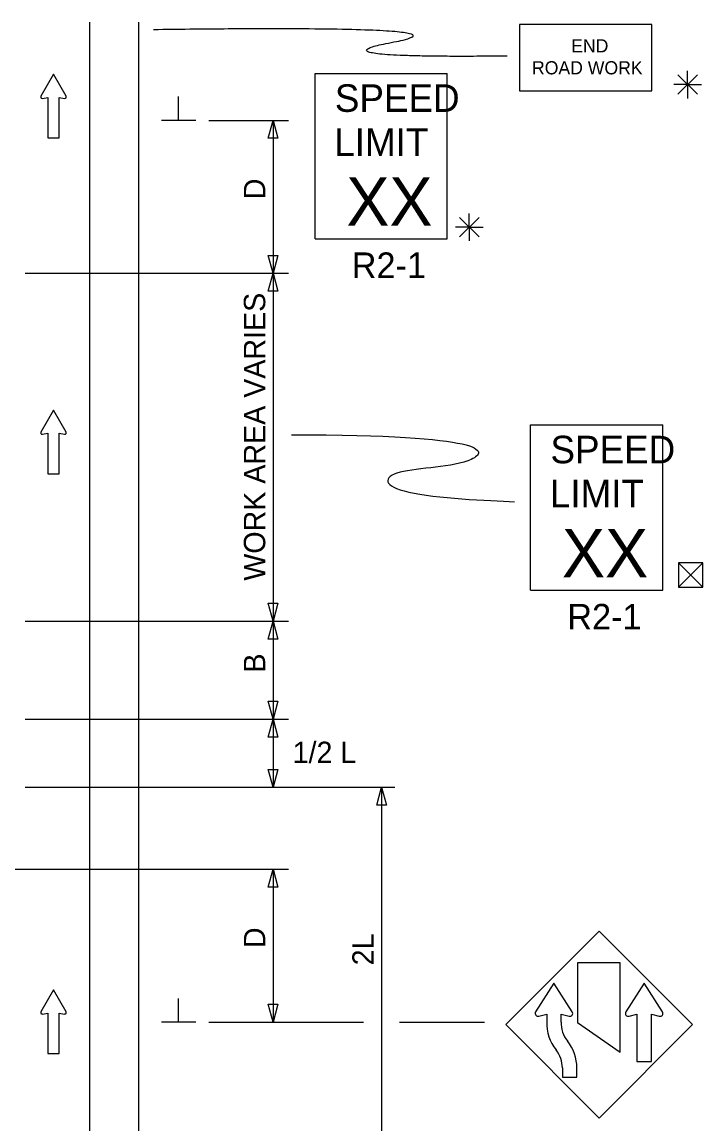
# Model space of a CAD drawing. Extents: x 16726 to 18482, y 5650 to 7013.
# Drawn here: x 16969.3 to 17191.9, y 6566.2 to 6926.4 of the extents above; entities that cross this region are included whole.
import ezdxf

# ---------------------------------------------------------------- set-up
doc = ezdxf.new("R2010")
doc.units = 0
for name, color, linetype in [('MT_SCRATCH_LEVEL_E', 7, 'Continuous'), ('PAVT_EDGE_EX', 7, 'Continuous'), ('TRAFFIC_SIGNS_PR', 7, 'Continuous'), ('TYPICAL_TEXT_DIMEN_PR', 7, 'Continuous')]:
    doc.layers.add(name, color=color, linetype=linetype)

msp = doc.modelspace()

# ---------------------------------------------------------------- linework, layer by layer
at = {"layer": 'MT_SCRATCH_LEVEL_E'}
for p, q in [((16979.53, 6909.41), (16975.42, 6902.17)), ((16983.68, 6902.17), (16979.53, 6909.41)), ((16975.91, 6901.48), (16977.68, 6901.8)), ((16977.68, 6901.8), (16977.68, 6888.54)), ((16981.42, 6888.54), (16981.42, 6901.8)), ((16981.42, 6901.8), (16983.2, 6901.48)), ((16977.68, 6888.54), (16981.42, 6888.54)), ((16979.53, 6799.6), (16975.42, 6792.36)), ((16983.68, 6792.36), (16979.53, 6799.6)), ((16975.91, 6791.67), (16977.68, 6791.99)), ((16977.68, 6791.99), (16977.68, 6778.73)), ((16981.42, 6778.73), (16981.42, 6791.99)), ((16981.42, 6791.99), (16983.2, 6791.67)), ((16977.68, 6778.73), (16981.42, 6778.73)), ((16979.53, 6610.04), (16975.42, 6602.8)), ((16983.68, 6602.8), (16979.53, 6610.04)), ((16975.91, 6602.12), (16977.68, 6602.43)), ((16977.68, 6602.43), (16977.68, 6589.18)), ((16981.42, 6589.18), (16981.42, 6602.43)), ((16981.42, 6602.43), (16983.2, 6602.12)), ((16977.68, 6589.18), (16981.42, 6589.18))]:
    msp.add_line(p, q, dxfattribs=at)
for centre, start, end in [((16975.83, 6901.94), 150.4248, 279.9638), ((16983.27, 6901.94), 260.0362, 29.7731), ((16975.83, 6792.13), 150.4248, 279.9638), ((16983.27, 6792.13), 260.0362, 29.7731), ((16975.83, 6602.58), 150.4248, 279.9638), ((16983.27, 6602.58), 260.0362, 29.7731)]:
    msp.add_arc(centre, 0.463, start, end, dxfattribs=at)
at = {"layer": 'PAVT_EDGE_EX'}
for p, q in [((16991.36, 6926.44), (16991.36, 6057.56)), ((17007.36, 6926.44), (17007.36, 6057.56))]:
    msp.add_line(p, q, dxfattribs=at)
at = {"layer": 'TRAFFIC_SIGNS_PR'}
for p, q in [((17065.08, 6909.61), (17108.28, 6909.61)), ((17065.08, 6855.61), (17065.08, 6909.61)), ((17108.28, 6855.61), (17108.28, 6909.61)), ((17065.08, 6855.61), (17108.28, 6855.61)), ((17135.57, 6794.71), (17178.77, 6794.71)), ((17135.57, 6740.71), (17135.57, 6794.71)), ((17178.77, 6740.71), (17178.77, 6794.71)), ((17135.57, 6740.71), (17178.77, 6740.71)), ((17157.98, 6629.21), (17127.43, 6598.66)), ((17188.53, 6598.66), (17157.98, 6629.21)), ((17127.43, 6598.66), (17157.98, 6568.11)), ((17157.98, 6568.11), (17188.53, 6598.66))]:
    msp.add_line(p, q, dxfattribs=at)
for points in [[(17131.96, 6904), (17175.16, 6904), (17175.16, 6925.6), (17131.96, 6925.6)], [(17150.88, 6618.83), (17150.88, 6599.32), (17164.84, 6589.62), (17164.84, 6618.83)]]:
    msp.add_lwpolyline(points, close=True, dxfattribs=at)
for points in [[(17149.2, 6602.83), (17143.2, 6612.24), (17137.21, 6602.83)], [(17178.7, 6602.83), (17172.71, 6612.24), (17166.72, 6602.83)], [(17138.26, 6601.41), (17140.84, 6602.12), (17140.84, 6599.61)], [(17145.56, 6599.49), (17145.56, 6602.12), (17148.15, 6601.41)], [(17167.77, 6601.41), (17170.35, 6602.12), (17170.35, 6586.59), (17175.07, 6586.59), (17175.07, 6602.12), (17177.66, 6601.41)], [(17145.98, 6584.47), (17145.97, 6581.49), (17150.7, 6581.49), (17150.7, 6584.47)]]:
    msp.add_lwpolyline(points, dxfattribs=at)
for centre, radius, start, end in [((17138.01, 6602.32), 0.945, 147.5204, 285.3986), ((17148.4, 6602.32), 0.947, 254.6828, 32.2708), ((17145.03, 6590.01), 11.81, 74.68, 74.6808), ((17159.16, 6609.16), 11.81, 212.4569, 212.4665), ((17167.52, 6602.32), 0.946, 147.5497, 285.3316), ((17177.91, 6602.32), 0.943, 254.6778, 32.4665), ((17188.67, 6609.16), 11.81, 212.4569, 212.4665), ((17155, 6599.19), 14.17, 178.3293, 218.5427), ((17155, 6599.19), 9.45, 178.1936, 218.5465), ((17133.75, 6599.86), 11.81, 358.1894, 0.0048), ((17136.52, 6584.47), 14.17, 0, 38.5422), ((17136.52, 6584.47), 9.45, 0, 38.5457)]:
    msp.add_arc(centre, radius, start, end, dxfattribs=at)
msp.add_open_spline([(17127.94, 6915.32), (17061.52, 6914.54), (17120.27, 6925.35), (17012.29, 6923.93)], degree=2, dxfattribs=at)
at = {"layer": 'TYPICAL_TEXT_DIMEN_PR'}
for p, q in [((17186.92, 6906), (17186.92, 6910.45)), ((17183.74, 6909.19), (17190.11, 6902.81)), ((17190.11, 6909.19), (17183.74, 6902.81)), ((17186.92, 6906), (17182.39, 6906)), ((17186.92, 6906), (17190.11, 6906)), ((17186.92, 6906), (17191.4, 6906)), ((17186.92, 6906), (17186.92, 6901.5)), ((17020.48, 6894.29), (17020.48, 6902.08)), ((17026.11, 6894.29), (17014.86, 6894.29)), ((17030.36, 6894.29), (17056.36, 6894.29)), ((17049.79, 6888.43), (17051.36, 6894.29)), ((17051.36, 6894.29), (17051.36, 6844.29)), ((17051.36, 6894.29), (17052.93, 6888.43)), ((17051.36, 6888.43), (17049.79, 6888.43)), ((17052.93, 6888.43), (17051.36, 6888.43)), ((17115.53, 6859.37), (17115.53, 6863.82)), ((17112.35, 6862.56), (17118.72, 6856.18)), ((17118.72, 6862.56), (17112.35, 6856.18)), ((17115.53, 6859.37), (17111, 6859.37)), ((17115.53, 6859.37), (17118.72, 6859.37)), ((17115.53, 6859.37), (17120.01, 6859.37)), ((17115.53, 6859.37), (17115.53, 6854.87)), ((17051.36, 6844.29), (17049.79, 6850.15)), ((17049.79, 6850.15), (17051.36, 6850.15)), ((17051.36, 6850.15), (17052.93, 6850.15)), ((17052.93, 6850.15), (17051.36, 6844.29)), ((16970.29, 6844.29), (17056.36, 6844.29)), ((17049.79, 6838.43), (17051.36, 6844.29)), ((17051.36, 6844.29), (17051.36, 6730.57)), ((17051.36, 6844.29), (17052.93, 6838.43)), ((17051.36, 6838.43), (17049.79, 6838.43)), ((17052.93, 6838.43), (17051.36, 6838.43)), ((17183.93, 6749.65), (17191.93, 6741.65)), ((17183.93, 6741.65), (17191.93, 6749.65)), ((17051.36, 6730.57), (17049.79, 6736.43)), ((17049.79, 6736.43), (17051.36, 6736.43)), ((17051.36, 6736.43), (17052.93, 6736.43)), ((17052.93, 6736.43), (17051.36, 6730.57)), ((16970.29, 6730.57), (17056.36, 6730.57)), ((17049.79, 6724.7), (17051.36, 6730.57)), ((17051.36, 6730.57), (17051.36, 6698.49)), ((17051.36, 6730.57), (17052.93, 6724.7)), ((17051.36, 6724.7), (17049.79, 6724.7)), ((17052.93, 6724.7), (17051.36, 6724.7)), ((17051.36, 6705.58), (17051.36, 6701.99)), ((17051.36, 6698.49), (17049.79, 6704.35)), ((17049.79, 6704.35), (17051.36, 6704.35)), ((17051.36, 6704.35), (17052.93, 6704.35)), ((17052.93, 6704.35), (17051.36, 6698.49)), ((16970.29, 6698.49), (17056.36, 6698.49)), ((17049.79, 6692.63), (17051.36, 6698.49)), ((17051.36, 6698.49), (17051.36, 6676.24)), ((17051.36, 6698.49), (17052.93, 6692.63)), ((17051.36, 6692.63), (17049.79, 6692.63)), ((17052.93, 6692.63), (17051.36, 6692.63)), ((17051.36, 6676.24), (17049.79, 6682.11)), ((17049.79, 6682.11), (17051.36, 6682.11)), ((17051.36, 6682.11), (17052.93, 6682.11)), ((17052.93, 6682.11), (17051.36, 6676.24)), ((16970.29, 6676.24), (17091.17, 6676.24)), ((17085.27, 6670.38), (17086.84, 6676.24)), ((17086.84, 6676.24), (17086.84, 6558.37)), ((17086.84, 6676.24), (17088.41, 6670.38)), ((17086.84, 6670.38), (17085.27, 6670.38)), ((17088.41, 6670.38), (17086.84, 6670.38)), ((16951.51, 6649.44), (17056.36, 6649.44)), ((17049.79, 6643.58), (17051.36, 6649.44)), ((17051.36, 6649.44), (17051.36, 6599.44)), ((17051.36, 6649.44), (17052.93, 6643.58)), ((17051.36, 6643.58), (17049.79, 6643.58)), ((17052.93, 6643.58), (17051.36, 6643.58)), ((17020.48, 6599.44), (17020.48, 6607.22)), ((17051.36, 6599.44), (17049.79, 6605.3)), ((17049.79, 6605.3), (17051.36, 6605.3)), ((17051.36, 6605.3), (17052.93, 6605.3)), ((17052.93, 6605.3), (17051.36, 6599.44)), ((17026.11, 6599.44), (17014.86, 6599.44)), ((17030.36, 6599.44), (17080.98, 6599.44)), ((17092.7, 6599.44), (17120.51, 6599.44))]:
    msp.add_line(p, q, dxfattribs=at)
msp.add_lwpolyline([(17183.93, 6749.65), (17183.93, 6741.65), (17191.93, 6741.65), (17191.93, 6749.65)], close=True, dxfattribs=at)
msp.add_open_spline([(17057.4, 6791.51), (17121.98, 6791.51), (17121.98, 6780.76), (17087.07, 6780.76), (17087.07, 6771.67), (17121.76, 6769.92), (17130.31, 6769.63)], degree=3, dxfattribs=at)

# ---------------------------------------------------------------- texts
at = {"layer": 'TRAFFIC_SIGNS_PR'}
for s, height, p in [('END', 4.31, (17148.84, 6916.52)), ('ROAD WORK', 4.31, (17136.02, 6909.34)), ('SPEED', 9, (17071.56, 6897.08)), ('LIMIT', 9, (17071.38, 6882.68)), ('XX', 15.785, (17075.33, 6859.84)), ('R2-1', 8.37, (17077.09, 6842.74)), ('SPEED', 9, (17142.06, 6782.18)), ('LIMIT', 9, (17141.88, 6767.78)), ('XX', 15.785, (17145.83, 6744.94)), ('R2-1', 8.37, (17147.58, 6727.84))]:
    msp.add_text(s, height=height, dxfattribs=at).set_placement(p)
at = {"layer": 'TYPICAL_TEXT_DIMEN_PR'}
for s, p in [('D', (17048.8, 6868.51)), ('WORK AREA VARIES', (17048.8, 6743.79)), ('B', (17048.8, 6713.76)), ('D', (17048.8, 6623.66)), ('2L', (17084.28, 6618.03))]:
    msp.add_text(s, height=7, rotation=90, dxfattribs=at).set_placement(p)
msp.add_text('1/2 L', height=7, dxfattribs=at).set_placement((17057.76, 6684.16))

doc.saveas('drawing.dxf')
